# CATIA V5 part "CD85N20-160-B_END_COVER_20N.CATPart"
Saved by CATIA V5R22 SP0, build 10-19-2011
Part number: CD85N20-160-B_END_COVER_20N
Revision: ANY
Definition: UNKNOWN
Nomenclature: CD85N20-160-B_END_COVER_20N
Source: Unknown
Bounding box of the stored display mesh (mm): x -12 to 12, y -12 to 12, z 0 to 35
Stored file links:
  U:\S9A\PER\CAO\Assemblage\Reservoir_Boite\Verin\Test_Poussoir_2\Test\CD85N20-160-B_END_COVER_20N.CATPart
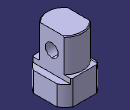
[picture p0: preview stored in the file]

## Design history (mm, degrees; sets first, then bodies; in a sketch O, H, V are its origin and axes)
Body1 "E-EXTEND" (main body)
  Solid1: solid without history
